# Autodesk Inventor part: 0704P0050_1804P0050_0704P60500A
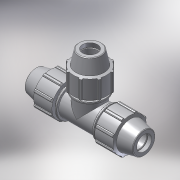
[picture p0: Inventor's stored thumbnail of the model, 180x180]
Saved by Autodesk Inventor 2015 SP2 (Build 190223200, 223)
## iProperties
Created: 2017-02
Part Number: 0704P0050_1804P0050_0704P60500A
Material: PVC-Piping
Description: PLASSON REPAIR TEE 50
Document SubType Name: Modeling
Designer: KIM
Mass: 92.6774 g
Surface Area: 199.44 cm^2
Volume: 66.1981 cm^3
Density: 1.4 g/cm^3
Appearance: Smooth - White
Author: Кирилл
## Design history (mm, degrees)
derived "0704P0.ipt"
feature "Solid1::0704P0.ipt"
tag "TaggingFeature1"
body "Solid1"
other parameters: "d4" = 10.5, "d5" = 31.5, "d7" = 96, "d11" = 4.2, "d13" = 120 deg, "d15" = 12 deg, "d16" = 83.52, "d18" = 2.5, "d19" = 35 deg, "d20" = 17.5 deg, "d21" = 89.28, "d23" = 0, "d25" = 360 deg, "d27" = 1.92, "d33" = 1, "d42" = 44.1, "d43" = 2.88, "d46" = 1.5, "d63" = 95, "d67" = 72, "d77" = 96, "d78" = 12 deg, "d79" = 126, "d80" = 120 deg, "d82" = 10.5, "d85" = 72, "d86" = 83.52, "d87" = 4.2, "d88" = 4.2, "d89" = 31.5, "d90" = 44.1, "d96" = 12.6, "d98" = 89.28, "d99" = 35 deg, "d100" = 17.5 deg, "d102" = 0, "d103" = 1.92, "d107" = 360 deg, "d109" = 1.5, "d112" = 2.5, "d118" = 360 deg, "d121" = 0, "d128" = 252, "d131" = 45, "d132" = 45, "d133" = 95, "d134" = 1.9, "d135" = 12.6, "d152" = 0, "d154" = 0, "d156" = 0, "d158" = 0, "E_" = 96, "A_" = 126, "l_" = 95, "H_" = 252
